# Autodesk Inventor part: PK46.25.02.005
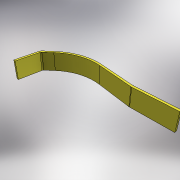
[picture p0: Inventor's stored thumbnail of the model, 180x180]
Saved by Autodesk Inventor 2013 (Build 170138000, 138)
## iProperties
Created: 2005-04
Part Number: PK46.25.02.005
Material: Steel, Mild
Document SubType Name: Sheet Metal
Designer: salex
Manufacturer: Standard
Standards Organization: Custom
Density: 7.86 g/cm^3
Sheet Metal Rule: Default
Mass: 35307.5 g
Surface Area: 5117.56 cm^2
Volume: 4492.05 cm^3
Author: salex
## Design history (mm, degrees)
node "ФлнОтгиб1"
body "Solid1"
sketch "Эскиз1"
  geometry: L1 (0, 0)-(-340, 0); L2 (-1042.494, -51.839)-(-1118.443, -116.892); L3 (-1118.443, -116.892)-(-1138.584, -331.646); L4 (-663.903, 53.731)-(-340, 0); L5 (-740, -405)-(-663.903, 53.731); L6 (-740, -405)-(-1042.494, -51.839); A1 r 465 centre (-740, -405) between (-663.903, 53.731) and (-1042.494, -51.839)
  constraints: 12 end point, 2 perpendicular, 2 point on circle, 2 tangent, 1 centre point, 1 horizontal, 1 other
  dimensions: "d1" = 340 distance of L1.start L1.end; "d2" = 400 horizontal distance of L5.start L1.end; "d3" = 465 radius of A1; "d4" = 405 distance from line of L5.start L1; "d5" = 100 distance of L2.start L2.end; "d6" = 150 distance from line of L3.end L2; "d7" = 50 deg angle of L5 L6; "d8" = 255 distance from line of L3.end L6
feature "Плакирование1" dims "d9" = 160, "d10" = 20 (= BendReliefWidth), "d12" = 40 (= MinimumRemnant), "d14" = 20 (= BendRadius), "d15" = 20, "Thickness" = 20
feature "Изгиб1" dims "d10" = 20 (= BendReliefWidth), "d11" = 10 (= BendReliefDepth), "d12" = 40 (= MinimumRemnant), "d13" = 20 (= BendRadius), "d14" = 20 (= BendRadius), "d15" = 20, "SeamGap" = 0.01, "Thickness" = 20
other parameters: "BendRadius" = 20 (= Thickness)
